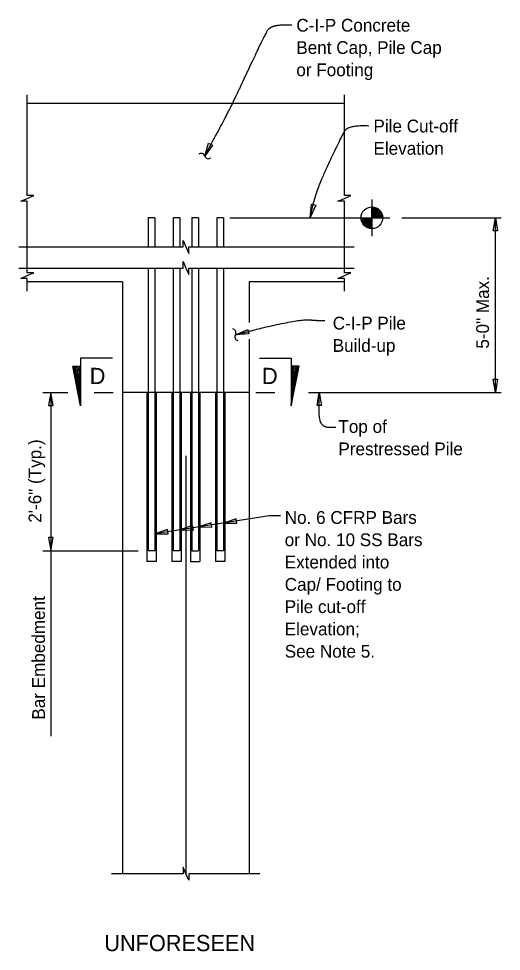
# Model space of a CAD drawing. Extents: x 112304.5 to 112376, y 111876.2 to 111935.5.
# Drawn here: x 112304.47 to 112312.08, y 111905.96 to 111920.68 of the extents above; entities that cross this region are included whole.
import ezdxf

# ---------------------------------------------------------------- set-up
doc = ezdxf.new("R2010")
doc.units = 0
for name, color, linetype in [('Border', 7, 'Continuous'), ('CL_Minor', 7, 'Continuous'), ('Patterning', 7, 'Continuous'), ('PlotBorder_dp', 7, 'Continuous'), ('SheetBorder_dp', 7, 'Continuous'), ('SheetLines_dp', 7, 'Continuous'), ('Symbols', 7, 'Continuous'), ('TextMisc', 7, 'Continuous')]:
    doc.layers.add(name, color=color, linetype=linetype)

msp = doc.modelspace()

# ---------------------------------------------------------------- linework, layer by layer
at = {"layer": 'Border'}
for p, q in [((112310.036, 111917.828), (112310.036, 111917.249)), ((112307.797, 111917.54), (112310.32, 111917.54)), ((112310.507, 111917.54), (112312.076, 111917.54)), ((112311.982, 111914.782), (112311.982, 111917.54)), ((112305.443, 111914.572), (112305.333, 111915.197)), ((112305.346, 111915.197), (112305.443, 111914.572)), ((112305.443, 111914.572), (112305.363, 111915.197)), ((112305.381, 111915.197), (112305.443, 111914.572)), ((112305.443, 111914.572), (112305.399, 111915.197)), ((112305.419, 111915.197), (112305.443, 111914.572)), ((112308.785, 111915.197), (112308.762, 111914.572)), ((112308.762, 111914.572), (112308.805, 111915.197)), ((112308.823, 111915.197), (112308.762, 111914.572)), ((112308.762, 111914.572), (112308.842, 111915.197)), ((112308.858, 111915.197), (112308.762, 111914.572)), ((112308.762, 111914.572), (112308.872, 111915.197)), ((112304.848, 111914.782), (112305.24, 111914.782)), ((112304.974, 111914.782), (112304.974, 111912.282)), ((112305.658, 111914.782), (112305.957, 111914.782)), ((112308.203, 111914.782), (112308.507, 111914.782)), ((112309.037, 111914.782), (112312.076, 111914.782)), ((112308.417, 111912.835), (112306.612, 111912.551)), ((112308.592, 111912.835), (112308.417, 111912.835)), ((112304.848, 111912.282), (112306.35, 111912.282)), ((112304.974, 111912.282), (112304.974, 111909.355))]:
    msp.add_line(p, q, dxfattribs=at)
for points in [[(112304.602, 111916.94), (112304.602, 111917.801), (112304.499, 111917.801), (112304.602, 111917.846), (112304.705, 111917.891), (112304.602, 111917.891), (112304.602, 111919.478)], [(112309.602, 111916.944), (112309.602, 111917.801), (112309.499, 111917.801), (112309.602, 111917.846), (112309.705, 111917.891), (112309.602, 111917.891), (112309.602, 111919.478)], [(112304.466, 111917.079), (112307.057, 111917.079), (112307.057, 111917.182), (112307.102, 111917.079), (112307.147, 111916.976), (112307.147, 111917.079), (112309.756, 111917.079)], [(112304.602, 111916.38), (112304.602, 111916.583), (112304.499, 111916.583), (112304.602, 111916.628), (112304.705, 111916.673), (112304.602, 111916.673), (112304.602, 111916.94)], [(112309.602, 111916.38), (112309.602, 111916.583), (112309.499, 111916.583), (112309.602, 111916.628), (112309.705, 111916.673), (112309.602, 111916.673), (112309.602, 111916.944)], [(112304.466, 111916.746), (112307.057, 111916.746), (112307.057, 111916.849), (112307.102, 111916.746), (112307.147, 111916.642), (112307.147, 111916.746), (112309.756, 111916.746)], [(112305.943, 111915.322), (112305.443, 111915.322), (112305.443, 111914.572), (112305.318, 111915.197), (112305.443, 111915.197)], [(112308.262, 111915.322), (112308.762, 111915.322), (112308.762, 111914.572), (112308.887, 111915.197), (112308.762, 111915.197)], [(112308.27, 111907.185), (112307.147, 111907.185), (112307.147, 111907.081), (112307.102, 111907.185), (112307.057, 111907.288), (112307.057, 111907.185), (112305.931, 111907.185)]]:
    msp.add_lwpolyline(points, dxfattribs=at)
for points in [[(112307.524, 111918.685), (112307.399, 111918.514), (112307.46, 111918.716)], [(112309.149, 111917.738), (112309.061, 111917.545), (112309.081, 111917.756)], [(112311.947, 111917.332), (112311.982, 111917.54), (112312.018, 111917.332)], [(112308.094, 111915.708), (112307.884, 111915.694), (112308.078, 111915.776)], [(112312.018, 111914.991), (112311.982, 111914.782), (112311.947, 111914.991)], [(112304.974, 111914.782), (112304.938, 111914.574), (112305.009, 111914.574)], [(112309.17, 111914.574), (112309.205, 111914.782), (112309.24, 111914.574)], [(112307.696, 111912.721), (112307.907, 111912.719), (112307.896, 111912.789)], [(112307.008, 111912.613), (112307.22, 111912.611), (112307.209, 111912.68)], [(112307.3, 111912.659), (112307.511, 111912.657), (112307.5, 111912.726)], [(112306.612, 111912.551), (112306.824, 111912.548), (112306.813, 111912.618)], [(112304.974, 111912.282), (112305.009, 111912.491), (112304.938, 111912.491)]]:
    msp.add_lwpolyline(points, close=True, dxfattribs=at)
for centre, start, end in [((112307.342, 111918.496), 17.7163, 129.4435), ((112307.456, 111918.532), 197.7163, 309.4435), ((112307.833, 111915.726), 327.4852, 79.2124), ((112307.934, 111915.662), 147.4852, 259.2124)]:
    msp.add_arc(centre, 0.0596, start, end, dxfattribs=at)
for points in [[(112307.399, 111918.514), (112307.757, 111919.173), (112307.958, 111919.596), (112308.341, 111920.417), (112308.457, 111920.6), (112308.774, 111920.585)], [(112309.061, 111917.545), (112309.058, 111917.54), (112309.173, 111918.005), (112309.556, 111918.826), (112309.672, 111919.009), (112309.989, 111918.993)], [(112307.884, 111915.694), (112307.881, 111915.689), (112308.289, 111915.801), (112308.942, 111915.939), (112309.162, 111915.918), (112309.292, 111915.918)], [(112309.205, 111914.782), (112309.202, 111914.777), (112309.191, 111914.335), (112309.298, 111914.228), (112309.458, 111914.236), (112309.465, 111914.236)]]:
    msp.add_open_spline(points, degree=2, dxfattribs=at)
at = {"layer": 'CL_Minor'}
msp.add_line((112307.102, 111913.782), (112307.102, 111907.185), dxfattribs=at)
at = {"layer": 'Patterning'}
for p, q in [((112306.612, 111912.282), (112306.508, 111912.282)), ((112307.008, 111912.282), (112306.904, 111912.282)), ((112307.196, 111912.282), (112307.3, 111912.282)), ((112307.696, 111912.282), (112307.592, 111912.282))]:
    msp.add_line(p, q, dxfattribs=at)
at = {"layer": 'PlotBorder_dp'}
for p, q in [((112309.602, 111919.346), (112304.602, 111919.346)), ((112306.102, 111916.527), (112304.602, 111916.527)), ((112306.102, 111916.527), (112306.102, 111913.782)), ((112308.102, 111916.527), (112308.102, 111915.888)), ((112309.602, 111916.527), (112308.102, 111916.527)), ((112308.102, 111915.624), (112308.102, 111913.782)), ((112306.102, 111913.782), (112306.102, 111907.185)), ((112308.102, 111913.782), (112308.102, 111907.185))]:
    msp.add_line(p, q, dxfattribs=at)
at = {"layer": 'SheetLines_dp'}
for p, q in [((112306.612, 111917.54), (112306.508, 111917.54)), ((112306.508, 111917.54), (112306.508, 111917.079)), ((112306.612, 111917.54), (112306.612, 111917.079)), ((112307.008, 111917.54), (112306.904, 111917.54)), ((112306.904, 111917.54), (112306.904, 111917.079)), ((112307.008, 111917.54), (112307.008, 111917.079)), ((112307.3, 111917.54), (112307.196, 111917.54)), ((112307.196, 111917.54), (112307.196, 111917.079)), ((112307.3, 111917.54), (112307.3, 111917.079)), ((112307.696, 111917.54), (112307.592, 111917.54)), ((112307.592, 111917.54), (112307.592, 111917.079)), ((112307.696, 111917.54), (112307.696, 111917.079)), ((112306.508, 111916.746), (112306.508, 111912.282)), ((112306.612, 111916.746), (112306.612, 111912.282)), ((112306.904, 111916.746), (112306.904, 111912.282)), ((112307.008, 111916.746), (112307.008, 111912.282)), ((112307.196, 111916.746), (112307.196, 111912.282)), ((112307.3, 111916.746), (112307.3, 111912.282)), ((112307.592, 111916.746), (112307.592, 111912.282)), ((112307.696, 111916.746), (112307.696, 111912.282))]:
    msp.add_line(p, q, dxfattribs=at)
at = {"layer": 'Symbols'}
for p, q in [((112309.909, 111917.425), (112310.164, 111917.655)), ((112309.922, 111917.413), (112310.151, 111917.668)), ((112309.935, 111917.401), (112310.137, 111917.679)), ((112309.951, 111917.392), (112310.122, 111917.689)), ((112309.967, 111917.383), (112310.106, 111917.697)), ((112309.983, 111917.377), (112310.089, 111917.703)), ((112310.001, 111917.372), (112310.072, 111917.708)), ((112310.018, 111917.369), (112310.054, 111917.711)), ((112310.036, 111917.369), (112310.036, 111917.712)), ((112309.865, 111917.54), (112310.208, 111917.54)), ((112309.866, 111917.522), (112310.207, 111917.558)), ((112309.868, 111917.504), (112310.204, 111917.576)), ((112309.873, 111917.487), (112310.2, 111917.593)), ((112309.88, 111917.47), (112310.193, 111917.61)), ((112309.888, 111917.454), (112310.185, 111917.626)), ((112309.898, 111917.439), (112310.175, 111917.641))]:
    msp.add_line(p, q, dxfattribs=at)
msp.add_circle((112310.036, 111917.54), 0.172, dxfattribs=at)
at = {"layer": 'TextMisc'}
for p, q in [((112308.102, 111914.782), (112306.102, 111914.782)), ((112306.487, 111914.782), (112306.487, 111912.116)), ((112306.633, 111914.782), (112306.633, 111912.116)), ((112306.883, 111914.782), (112306.883, 111912.116)), ((112307.029, 111914.782), (112307.029, 111912.116)), ((112307.175, 111914.782), (112307.175, 111912.116)), ((112307.321, 111914.782), (112307.321, 111912.116)), ((112307.571, 111914.782), (112307.571, 111912.116)), ((112307.717, 111914.782), (112307.717, 111912.116)), ((112306.633, 111912.116), (112306.487, 111912.116)), ((112307.029, 111912.116), (112306.883, 111912.116)), ((112307.175, 111912.116), (112307.321, 111912.116)), ((112307.717, 111912.116), (112307.571, 111912.116))]:
    msp.add_line(p, q, dxfattribs=at)

# ---------------------------------------------------------------- texts
at = {"layer": 'Border'}
for s, height, p in [('C-I-P Concrete', 0.2016, (112308.844, 111920.478)), ('Bent Cap, Pile Cap', 0.2016, (112308.844, 111920.126)), ('or Footing', 0.2016, (112308.844, 111919.774)), ('Pile Cut-off', 0.2016, (112310.06, 111918.887)), ('Elevation', 0.2016, (112310.06, 111918.535)), ('No. 6 CFRP Bars', 0.2016, (112308.661, 111912.708)), ('or No. 10 SS Bars', 0.2016, (112308.661, 111912.356)), ('Extended into', 0.2016, (112308.661, 111912.004)), ('Cap/ Footing to', 0.2016, (112308.661, 111911.652)), ('Pile cut-off', 0.2016, (112308.661, 111911.3)), ('Elevation;', 0.2016, (112308.661, 111910.948)), ('See Note 5.', 0.2016, (112308.661, 111910.596)), ('UNFORESEEN', 0.256, (112305.816, 111905.963))]:
    msp.add_text(s, height=height, dxfattribs=at).set_placement(p)
msp.add_text('5-0" Max.', height=0.2016, rotation=90, dxfattribs=at).set_placement((112311.882, 111915.474))
at = {"layer": 'SheetBorder_dp'}
for s, height, p in [('C-I-P Pile', 0.2016, (112309.418, 111915.776)), ('Build-up', 0.2016, (112309.418, 111915.423)), ('D', 0.256, (112305.586, 111914.915)), ('D', 0.256, (112308.303, 111914.915)), ('Top of', 0.2016, (112309.507, 111914.144)), ('Prestressed Pile', 0.2016, (112309.507, 111913.791))]:
    msp.add_text(s, height=height, dxfattribs=at).set_placement(p)
for s, p in [('2\'-6" (Typ.)', (112304.823, 111912.726)), ('Bar Embedment', (112304.88, 111909.618))]:
    msp.add_text(s, height=0.2016, rotation=90, dxfattribs=at).set_placement(p)

doc.saveas('drawing.dxf')
